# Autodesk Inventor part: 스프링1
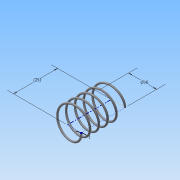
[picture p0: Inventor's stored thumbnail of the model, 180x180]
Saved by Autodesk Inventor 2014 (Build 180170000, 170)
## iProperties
Created: 2015-06
Part Number: 스프링1
Material: 강철, 연강
Document SubType Name: Modeling
Designer: Administrator
Density: 7.86 g/cm^3
Appearance: 강철
Mass: 1.53479 g
Surface Area: 7.89194 cm^2
Volume: 0.195266 cm^3
Author: Administrator
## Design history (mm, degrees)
sketch "스케치1"
  geometry: L1 (0, 0)-(8, 0); L2 (8, 0)-(8, 21.5); L3 (8, 21.5)-(0, 21.5); L4 (0, 21.5)-(0, 0); C1 r 0.5 at (8, 0)
  constraints: 8 end point, 2 parallel, 1 centre point, 1 coincident, 1 horizontal, 1 perpendicular
  dimensions: "d0" = 21.5 distance of L3.end L1.start (derived); "d1" = 16 diameter of L2 L4; "d2" = 1 diameter of C1
feature "코일1" sketch "스케치1" pitch "d3" = 10; turns "d5" = 5; dims "d4" = 21.5 (= d0), "d6" = 0, angle "d7" = 90 deg, angle "d8" = 90 deg, "d9" = 0, "d10" = 0
sketch "스케치2"
  geometry: L1 (-8.5, 0)-(-7.5, 0) reference; 1 further point
  constraints: 1 horizontal alignment
extrude "돌출1" cut sketch "스케치2" distance "d11" = 10; taper "d12" = 0 deg
node "작업 평면1"
sketch "스케치3"
  geometry: L1 (-7.5, 0)-(-8.5, 0) reference; 1 further point
  constraints: 1 horizontal alignment
extrude "돌출2" cut sketch "스케치3" distance "d14" = 10; taper "d15" = 0 deg
node "솔리드1"
node "절단 모서리 투영1"
node "절단 모서리 투영2"
other parameters: "d13" = 21.5 (= d0)
